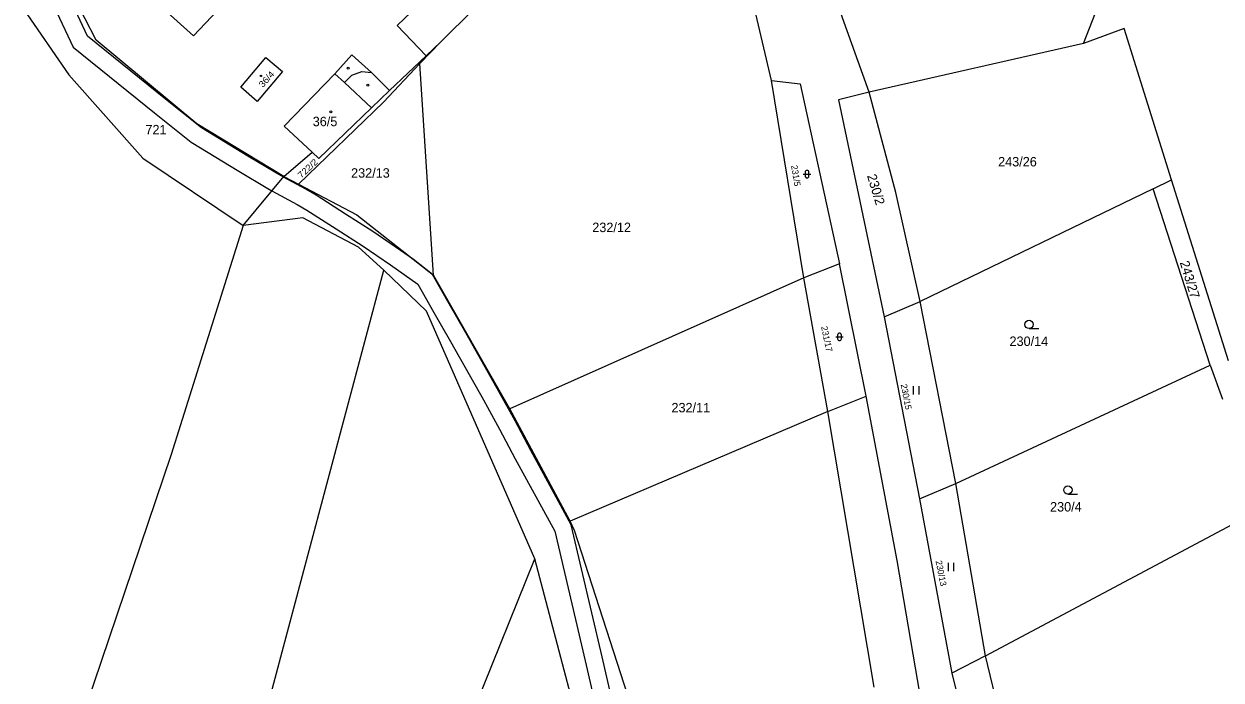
# Model space of a CAD drawing. Extents: x -701211 to -698780, y -1014269 to -1012378.
# Drawn here: x -701013.5 to -700798.3, y -1012938.3 to -1012820.3 of the extents above; entities that cross this region are included whole.
import ezdxf
from ezdxf.enums import TextEntityAlignment as Align

# ---------------------------------------------------------------- set-up
doc = ezdxf.new("R2010")
doc.units = 0
doc.header["$LTSCALE"] = 0.68
for name, color, linetype, lineweight in [('1', 7, 'Continuous', 25), ('13', 7, 'Continuous', 13), ('3', 7, 'Continuous', 25), ('4', 7, 'Continuous', 13), ('5', 7, 'Continuous', 25)]:
    doc.layers.add(name, color=color, linetype=linetype, lineweight=lineweight)
doc.layers.add('2', color=7, linetype='Continuous')

msp = doc.modelspace()

# ---------------------------------------------------------------- linework, layer by layer
at = {"layer": '1'}
for p, q in [((-700823.05, -1012823.84), (-700800.19, -1012765.01)), ((-700937.26, -1012822.19), (-700925.63, -1012810.81)), ((-701000.52, -1012823.26), (-701005.28, -1012814.01)), ((-700946.4, -1012820.6), (-700942.56, -1012816.95)), ((-700879.16, -1012830.48), (-700882.58, -1012815.63)), ((-701013.51, -1012817.71), (-701005.43, -1012829.46)), ((-700861.58, -1012832.59), (-700866.7, -1012818.38)), ((-700815.74, -1012821.11), (-700823.05, -1012823.84)), ((-700807.25, -1012848.34), (-700815.74, -1012821.11)), ((-700982.44, -1012838.28), (-701000.52, -1012823.26)), ((-700938.56, -1012823.54), (-700942.34, -1012827.44)), ((-700941.23, -1012826.06), (-700938.56, -1012823.54)), ((-700938.56, -1012823.54), (-700937.26, -1012822.19)), ((-700823.05, -1012823.84), (-700861.58, -1012832.59)), ((-700974.53, -1012831.68), (-700970.05, -1012826.35)), ((-700970.05, -1012826.35), (-700967.02, -1012828.89)), ((-700942.34, -1012827.44), (-700948.87, -1012834.37)), ((-700939.91, -1012865.5), (-700942.34, -1012827.44)), ((-701005.43, -1012829.46), (-700992.16, -1012844.45)), ((-700967.02, -1012828.89), (-700971.6, -1012834.27)), ((-700957.64, -1012829.26), (-700966.73, -1012838.7)), ((-700957.64, -1012829.26), (-700955.91, -1012830.87)), ((-700879.16, -1012830.48), (-700874, -1012831.09)), ((-700873.31, -1012865.97), (-700879.16, -1012830.48)), ((-700971.6, -1012834.27), (-700974.53, -1012831.68)), ((-700955.91, -1012830.87), (-700951.03, -1012835.39)), ((-700951.03, -1012835.39), (-700947.82, -1012832.28)), ((-700874, -1012831.09), (-700866.89, -1012863.44)), ((-700861.58, -1012832.59), (-700867.07, -1012833.98)), ((-700856.8, -1012850.61), (-700861.58, -1012832.59)), ((-700867.07, -1012833.98), (-700858.87, -1012872.99)), ((-700960.49, -1012844.54), (-700951.03, -1012835.39)), ((-700966.79, -1012847.75), (-700982.44, -1012838.28)), ((-700966.73, -1012838.7), (-700961.7, -1012843.4)), ((-700966.79, -1012847.75), (-700961.7, -1012843.4)), ((-700961.7, -1012843.4), (-700960.49, -1012844.54)), ((-700992.16, -1012844.45), (-700974.12, -1012856.57)), ((-700974.12, -1012856.57), (-700966.79, -1012847.75)), ((-700966.79, -1012847.75), (-700964.15, -1012849.1)), ((-700810.52, -1012849.97), (-700852.4, -1012870.24)), ((-700810.52, -1012849.97), (-700807.25, -1012848.34)), ((-700800.3, -1012881.65), (-700810.52, -1012849.97)), ((-700797, -1012880.92), (-700807.25, -1012848.34)), ((-700852.4, -1012870.24), (-700856.8, -1012850.61)), ((-700963.36, -1012855.2), (-700974.12, -1012856.57)), ((-700953.35, -1012860.46), (-700963.36, -1012855.2)), ((-700953.69, -1012854.66), (-700939.91, -1012865.5)), ((-700974.12, -1012856.57), (-700987.06, -1012897.76)), ((-700948.79, -1012864.57), (-700953.35, -1012860.46)), ((-700941.16, -1012871.94), (-700948.79, -1012864.57)), ((-700866.89, -1012863.44), (-700873.31, -1012865.97)), ((-700862.11, -1012887.23), (-700866.89, -1012863.44)), ((-700926.14, -1012889.54), (-700939.91, -1012865.5)), ((-700873.31, -1012865.97), (-700926.14, -1012889.54)), ((-700868.99, -1012890.01), (-700873.31, -1012865.97)), ((-700858.87, -1012872.99), (-700852.4, -1012870.24)), ((-700846, -1012902.94), (-700852.4, -1012870.24)), ((-700921.68, -1012916.49), (-700941.16, -1012871.94)), ((-700858.87, -1012872.99), (-700852.56, -1012905.69)), ((-700846, -1012902.94), (-700800.3, -1012881.65)), ((-700800.3, -1012881.65), (-700798.09, -1012887.81)), ((-700868.99, -1012890.01), (-700862.11, -1012887.23)), ((-700856.53, -1012916.78), (-700862.11, -1012887.23)), ((-700915.34, -1012909.72), (-700926.14, -1012889.54)), ((-700868.99, -1012890.01), (-700915.34, -1012909.72)), ((-700860.7, -1012939.55), (-700868.99, -1012890.01)), ((-700987.06, -1012897.76), (-701004.28, -1012948.73)), ((-700852.56, -1012905.69), (-700846, -1012902.94)), ((-700840.69, -1012933.93), (-700846, -1012902.94)), ((-700852.56, -1012905.69), (-700846.71, -1012937.05)), ((-700840.69, -1012933.93), (-700788.72, -1012906.25)), ((-700914.53, -1012911.43), (-700915.34, -1012909.72)), ((-700894, -1012975.02), (-700914.53, -1012911.43)), ((-700938.57, -1012958.49), (-700921.68, -1012916.49)), ((-700905.7, -1012977.03), (-700921.68, -1012916.49)), ((-700851.85, -1012944.35), (-700856.53, -1012916.78)), ((-700840.69, -1012933.93), (-700846.71, -1012937.05)), ((-700836.72, -1012950.14), (-700840.69, -1012933.93)), ((-700846.71, -1012937.05), (-700841.75, -1012957.5))]:
    msp.add_line(p, q, dxfattribs=at)
for points in [[(-700947.82, -1012832.28), (-700941.23, -1012826.06), (-700946.4, -1012820.6)], [(-700948.87, -1012834.37), (-700964.15, -1012849.1), (-700953.69, -1012854.66)], [(-700996.75, -1013042.57), (-700969.3, -1012941.55), (-700948.79, -1012864.57)]]:
    msp.add_lwpolyline(points, dxfattribs=at)
at = {"layer": '13'}
for points in [[(-700906.86, -1012945.88), (-700909.56, -1012934.11), (-700915.12, -1012910.36), (-700922.42, -1012897.02), (-700925.23, -1012891.69), (-700928.14, -1012886.39), (-700934.1, -1012875.88), (-700937.1, -1012870.66), (-700940.05, -1012865.39), (-700943.48, -1012862.69), (-700945.81, -1012861.04), (-700950.82, -1012857.64), (-700955.68, -1012854.51), (-700961.01, -1012851.11), (-700962.85, -1012850.04), (-700966.87, -1012847.85), (-700968.13, -1012847.17), (-700973.26, -1012844.11), (-700981.61, -1012839), (-700988.07, -1012833.84), (-701002.1, -1012822.49), (-701004.74, -1012816.87)], [(-701007.6, -1012818.23), (-701004.64, -1012824.49), (-700990.05, -1012836.3), (-700983.43, -1012841.6), (-700974.9, -1012846.81), (-700969.69, -1012849.91), (-700968.93, -1012850.33), (-700964.39, -1012852.8), (-700962.65, -1012853.81), (-700957.38, -1012857.17), (-700952.56, -1012860.28), (-700947.61, -1012863.64), (-700942.7, -1012867.11), (-700939.84, -1012872.22), (-700936.84, -1012877.44), (-700930.9, -1012887.93), (-700928.01, -1012893.19), (-700925.2, -1012898.52), (-700918.1, -1012911.5), (-700912.64, -1012934.83), (-700909.96, -1012946.54)]]:
    msp.add_lwpolyline(points, dxfattribs=at)
at = {"layer": '3'}
for p, q in [((-700873.421, -1012847.321), (-700872.079, -1012847.321)), ((-700873.085, -1012846.985), (-700873.085, -1012847.656)), ((-700872.415, -1012847.656), (-700872.415, -1012846.985)), ((-700832.843, -1012875.1), (-700831.093, -1012875.1)), ((-700867.581, -1012876.591), (-700866.239, -1012876.591)), ((-700867.245, -1012876.255), (-700867.245, -1012876.926)), ((-700866.575, -1012876.926), (-700866.575, -1012876.255)), ((-700853.621, -1012886.94), (-700853.621, -1012885.44)), ((-700852.62, -1012886.94), (-700852.62, -1012885.44)), ((-700825.863, -1012904.87), (-700824.113, -1012904.87)), ((-700847.341, -1012918.69), (-700847.341, -1012917.19)), ((-700846.34, -1012918.69), (-700846.34, -1012917.19))]:
    msp.add_line(p, q, dxfattribs=at)
for centre in [(-700832.8429, -1012874.3498), (-700825.8629, -1012904.1198)]:
    msp.add_circle(centre, 0.75, dxfattribs=at)
for centre, start, end in [((-700872.75, -1012846.9856), 0, 180), ((-700872.75, -1012847.6556), 180, 359.98789), ((-700866.91, -1012876.2556), 0, 180), ((-700866.91, -1012876.9256), 180, 359.98789)]:
    msp.add_arc(centre, 0.335, start, end, dxfattribs=at)
at = {"layer": '4'}
for p, q in [((-700983.03, -1012822.46), (-700994.72, -1012811.87)), ((-700983.03, -1012822.46), (-700974.94, -1012813.76)), ((-700957.64, -1012829.26), (-700954.56, -1012825.85)), ((-700954.56, -1012825.85), (-700951.06, -1012829.07)), ((-700955.91, -1012830.87), (-700954.59, -1012829.52)), ((-700954.59, -1012829.52), (-700952.76, -1012828.86)), ((-700952.76, -1012828.86), (-700951.06, -1012829.07)), ((-700951.06, -1012829.07), (-700948, -1012832.1)), ((-700948, -1012832.1), (-700947.82, -1012832.28))]:
    msp.add_line(p, q, dxfattribs=at)
at = {"layer": '5'}
for centre, radius in [((-700955.2468, -1012828.2792), 0.175), ((-700970.9046, -1012829.6594), 0.1172), ((-700951.6968, -1012831.3392), 0.175), ((-700958.3268, -1012836.1392), 0.175)]:
    msp.add_circle(centre, radius, dxfattribs=at)

# ---------------------------------------------------------------- texts
at = {"layer": '2', "width": 1.1}
for s, rotation, p in [('36/4', 48, (-700969.4822, -1012830.6354)), ('722/2', 43, (-700962.1072, -1012846.7135))]:
    msp.add_text(s, height=1.14, rotation=rotation, dxfattribs=at).set_placement(p, align=Align.CENTER)
at = {"layer": '2'}
for s, p in [('36/5', (-700961.6, -1012838.705)), ('721', (-700991.67, -1012840.175)), ('230/14', (-700836.35, -1012878.225)), ('230/4', (-700829.06, -1012907.995))]:
    msp.add_text(s, height=1.7, dxfattribs=at).set_placement(p)
for s, p in [('243/26', (-700834.92, -1012845.935)), ('232/13', (-700951.23, -1012847.965)), ('232/12', (-700907.87, -1012857.745)), ('232/11', (-700893.64, -1012890.165))]:
    msp.add_text(s, height=1.7, dxfattribs=at).set_placement(p, align=Align.CENTER)
for s, height, rotation, p in [('231/5', 1.14, 279, (-700875.3143, -1012847.6798)), ('243/27', 1.7, 287, (-700804.7468, -1012866.5305)), ('231/17', 1.14, 282, (-700869.7459, -1012877.079)), ('230/15', 1.14, 281, (-700855.4787, -1012887.4692)), ('230/13', 1.14, 281, (-700849.1987, -1012919.1992))]:
    msp.add_text(s, height=height, rotation=rotation, dxfattribs=at).set_placement(p, align=Align.CENTER)
msp.add_text('230/2', height=1.7, rotation=287, dxfattribs=at).set_placement((-700861.986, -1012847.614))

doc.saveas('drawing.dxf')
